(* Logix 5000 project; controller New_CR30 vendor 1 type 14 code 155 rev 21.11; software revision 21.00 *)

TASK MainTask (continuous, watchdog 500 ms) : MainProgram

MODULES
   Local : vendor 1 type 14 code 155 (PointIO 0, rev 21.11)
      CR30 : 440C-CR30-22BBB (Ethernet 192.168.1.30, rev 8.1, Output RPI 60 ms)
      Discrete_IO : Embedded (PointIO 1, rev 21.11, Output RPI 20 ms)
END_MODULES

TYPE STRING_24 :   // string type
STRUCT
   LEN : DINT;
   DATA : SINT[24];
END_STRUCT
END_TYPE

ADD_ON_INSTRUCTION AOI_440C_CR30   (* revision 1.0, vendor Rockwell Automation *)
VAR_INPUT
   Set_FaceplateAnimation : INT;
END_VAR
VAR_OUTPUT
   Sts_Value1 : REAL; {access Read Only}
   Sts_Value2 : REAL; {access Read Only}
   Sts_Value3 : REAL; {access Read Only}
END_VAR
VAR_IN_OUT
   Input_CR30 : AB:440C_CR30:I:0; {required}
   Output_CR30 : AB:440C_CR30:O:0; {required}
END_VAR
VAR_INPUT
   Val_FaultCode : DINT; {visible}
END_VAR
VAR_OUTPUT
   Sts_Value4 : REAL; {access Read Only}
END_VAR
VAR_INPUT
   Val_MinorFaultType : DINT; {required}
   Val_MinorFault : DINT; {required}
   Val_MajorFaultType : DINT; {required}
   Val_MajorFault : DINT; {required}
END_VAR
VAR_OUTPUT
   Sts_ProgramModeEnabled : DINT;
   Sts_CommFault : BOOL; {access Read Only}
   Sts_MinorFault : BOOL; {access Read Only}
   Sts_MajorFault : BOOL; {access Read Only}
   Sts_RunMode : BOOL; {access Read Only}
END_VAR
VAR
   Set_OutputName : STRING_24[25];
   Set_InputName : STRING_24[30] := ([0] := '1');
   Set_DeviceNameOper : STRING := '440C-CR30';
   Val_FaultDescription : STRING_24[30];
   Set_SMFInputName : STRING_24[30];
   Set_SOFInputName : STRING_24[30];
   Val_VerficationID : DINT;
END_VAR

ROUTINE Logic   (* ladder *)
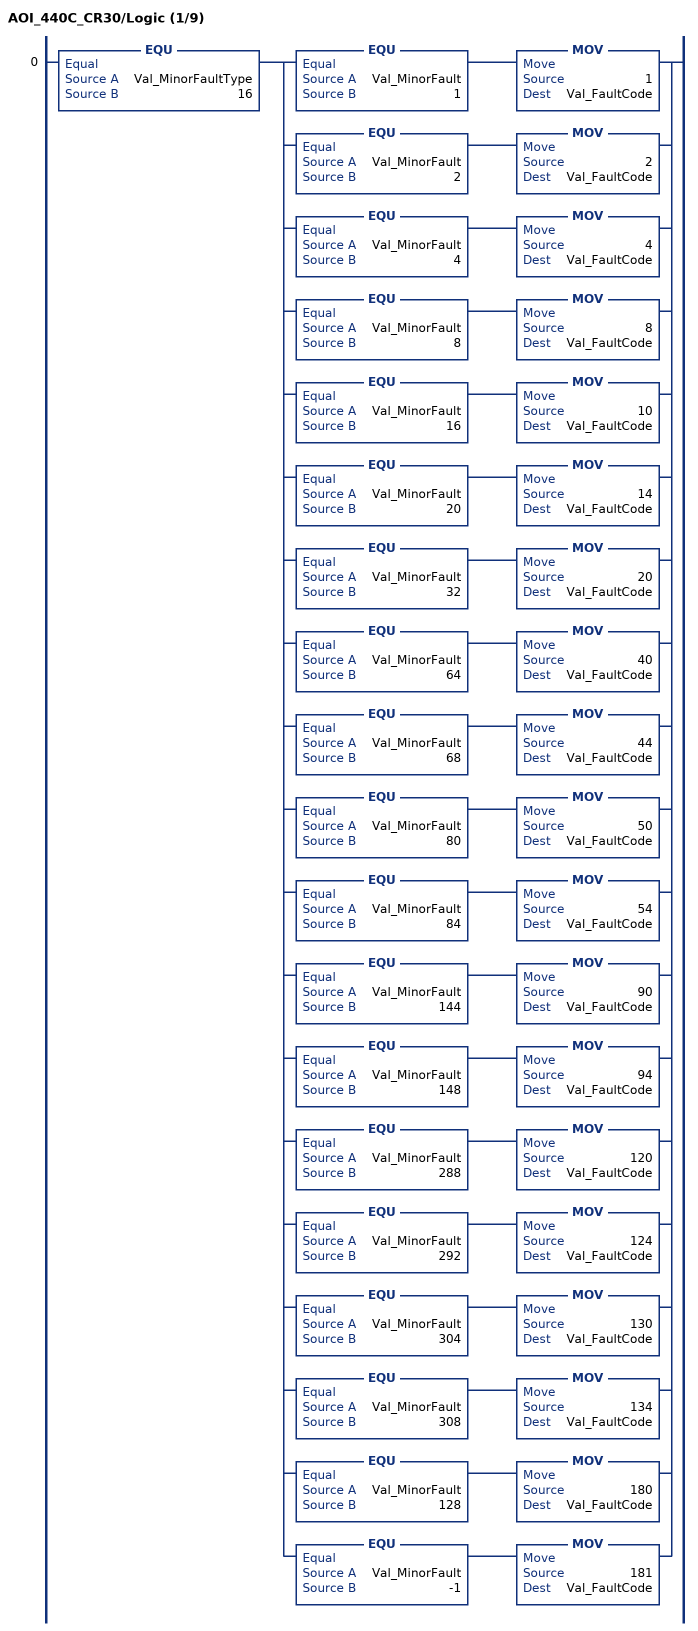
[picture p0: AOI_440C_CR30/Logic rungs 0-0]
   0: EQU(Val_MinorFaultType,16)[EQU(Val_MinorFault,1) MOV(1,Val_FaultCode) ,EQU(Val_MinorFault,2) MOV(2,Val_FaultCode) ,EQU(Val_MinorFault,4) MOV(4,Val_FaultCode) ,EQU(Val_MinorFault,8) MOV(8,Val_FaultCode) ,EQU(Val_MinorFault,16) MOV(10,Val_FaultCode) ,EQU(Val_MinorFault,20) MOV(14,Val_FaultCode) ,EQU(Val_MinorFault,32) MOV(20,Val_FaultCode) ,EQU(Val_MinorFault,64) MOV(40,Val_FaultCode) ,EQU(Val_MinorFault,68) MOV(44,Val_FaultCode) ,EQU(Val_MinorFault,80) MOV(50,Val_FaultCode) ,EQU(Val_MinorFault,84) MOV(54,Val_FaultCode) ,EQU(Val_MinorFault,144) MOV(90,Val_FaultCode) ,EQU(Val_MinorFault,148) MOV(94,Val_FaultCode) ,EQU(Val_MinorFault,288) MOV(120,Val_FaultCode) ,EQU(Val_MinorFault,292) MOV(124,Val_FaultCode) ,EQU(Val_MinorFault,304) MOV(130,Val_FaultCode) ,EQU(Val_MinorFault,308) MOV(134,Val_FaultCode) ,EQU(Val_MinorFault,128) MOV(180,Val_FaultCode) ,EQU(Val_MinorFault,-1) MOV(181,Val_FaultCode) ];
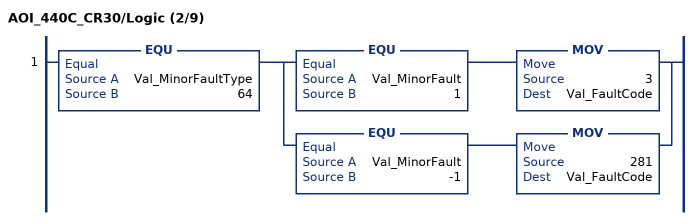
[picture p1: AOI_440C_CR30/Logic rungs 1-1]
   1: EQU(Val_MinorFaultType,64)[EQU(Val_MinorFault,1) MOV(3,Val_FaultCode) ,EQU(Val_MinorFault,-1) MOV(281,Val_FaultCode) ];
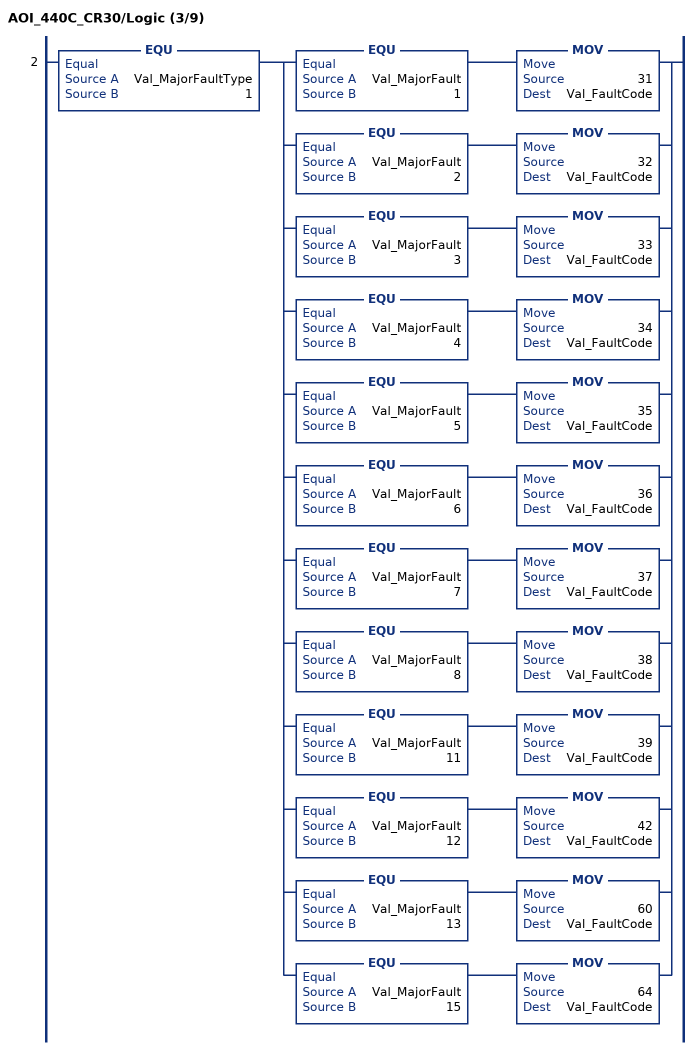
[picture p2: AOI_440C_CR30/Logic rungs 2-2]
   2: EQU(Val_MajorFaultType,1)[EQU(Val_MajorFault,1) MOV(31,Val_FaultCode) ,EQU(Val_MajorFault,2) MOV(32,Val_FaultCode) ,EQU(Val_MajorFault,3) MOV(33,Val_FaultCode) ,EQU(Val_MajorFault,4) MOV(34,Val_FaultCode) ,EQU(Val_MajorFault,5) MOV(35,Val_FaultCode) ,EQU(Val_MajorFault,6) MOV(36,Val_FaultCode) ,EQU(Val_MajorFault,7) MOV(37,Val_FaultCode) ,EQU(Val_MajorFault,8) MOV(38,Val_FaultCode) ,EQU(Val_MajorFault,11) MOV(39,Val_FaultCode) ,EQU(Val_MajorFault,12) MOV(42,Val_FaultCode) ,EQU(Val_MajorFault,13) MOV(60,Val_FaultCode) ,EQU(Val_MajorFault,15) MOV(64,Val_FaultCode) ];
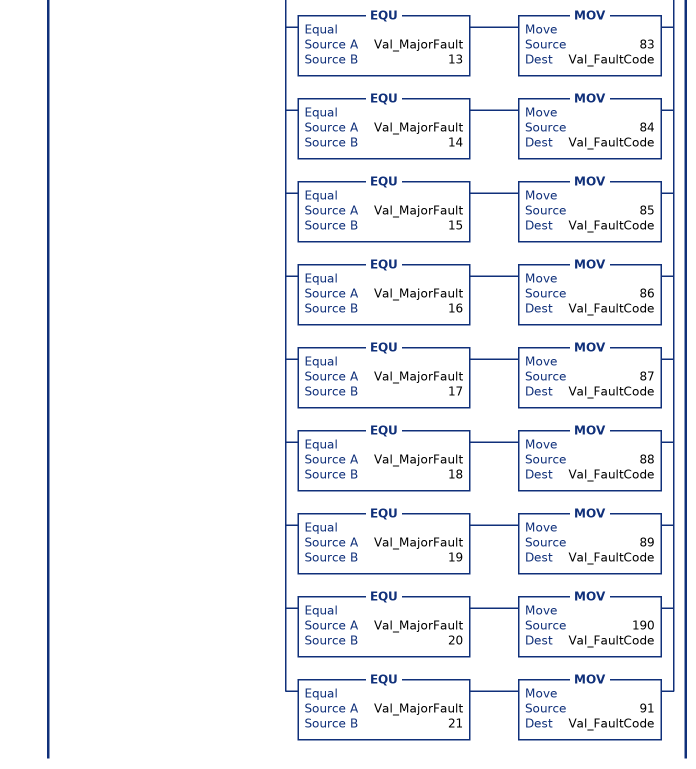
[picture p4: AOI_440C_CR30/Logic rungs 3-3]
   3: EQU(Val_MajorFaultType,2)[EQU(Val_MajorFault,1) MOV(71,Val_FaultCode) ,EQU(Val_MajorFault,2) MOV(72,Val_FaultCode) ,EQU(Val_MajorFault,3) MOV(73,Val_FaultCode) ,EQU(Val_MajorFault,4) MOV(74,Val_FaultCode) ,EQU(Val_MajorFault,5) MOV(75,Val_FaultCode) ,EQU(Val_MajorFault,6) MOV(76,Val_FaultCode) ,EQU(Val_MajorFault,7) MOV(77,Val_FaultCode) ,EQU(Val_MajorFault,8) MOV(78,Val_FaultCode) ,EQU(Val_MajorFault,9) MOV(79,Val_FaultCode) ,EQU(Val_MajorFault,10) MOV(80,Val_FaultCode) ,EQU(Val_MajorFault,11) MOV(81,Val_FaultCode) ,EQU(Val_MajorFault,12) MOV(82,Val_FaultCode) ,EQU(Val_MajorFault,13) MOV(83,Val_FaultCode) ,EQU(Val_MajorFault,14) MOV(84,Val_FaultCode) ,EQU(Val_MajorFault,15) MOV(85,Val_FaultCode) ,EQU(Val_MajorFault,16) MOV(86,Val_FaultCode) ,EQU(Val_MajorFault,17) MOV(87,Val_FaultCode) ,EQU(Val_MajorFault,18) MOV(88,Val_FaultCode) ,EQU(Val_MajorFault,19) MOV(89,Val_FaultCode) ,EQU(Val_MajorFault,20) MOV(190,Val_FaultCode) ,EQU(Val_MajorFault,21) MOV(91,Val_FaultCode) ];
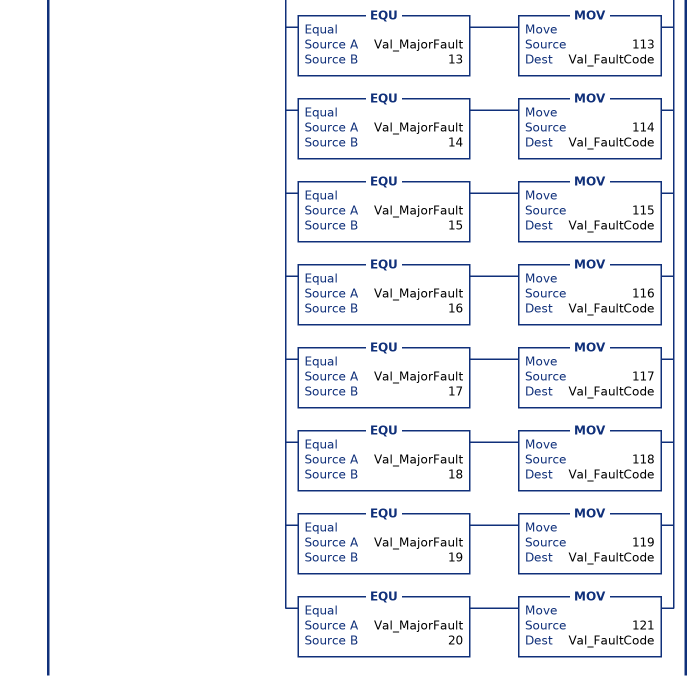
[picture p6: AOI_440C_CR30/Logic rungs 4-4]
   4: EQU(Val_MajorFaultType,4)[EQU(Val_MajorFault,1) MOV(101,Val_FaultCode) ,EQU(Val_MajorFault,2) MOV(102,Val_FaultCode) ,EQU(Val_MajorFault,3) MOV(103,Val_FaultCode) ,EQU(Val_MajorFault,4) MOV(104,Val_FaultCode) ,EQU(Val_MajorFault,5) MOV(105,Val_FaultCode) ,EQU(Val_MajorFault,6) MOV(106,Val_FaultCode) ,EQU(Val_MajorFault,7) MOV(107,Val_FaultCode) ,EQU(Val_MajorFault,8) MOV(108,Val_FaultCode) ,EQU(Val_MajorFault,9) MOV(109,Val_FaultCode) ,EQU(Val_MajorFault,10) MOV(110,Val_FaultCode) ,EQU(Val_MajorFault,11) MOV(111,Val_FaultCode) ,EQU(Val_MajorFault,12) MOV(112,Val_FaultCode) ,EQU(Val_MajorFault,13) MOV(113,Val_FaultCode) ,EQU(Val_MajorFault,14) MOV(114,Val_FaultCode) ,EQU(Val_MajorFault,15) MOV(115,Val_FaultCode) ,EQU(Val_MajorFault,16) MOV(116,Val_FaultCode) ,EQU(Val_MajorFault,17) MOV(117,Val_FaultCode) ,EQU(Val_MajorFault,18) MOV(118,Val_FaultCode) ,EQU(Val_MajorFault,19) MOV(119,Val_FaultCode) ,EQU(Val_MajorFault,20) MOV(121,Val_FaultCode) ];
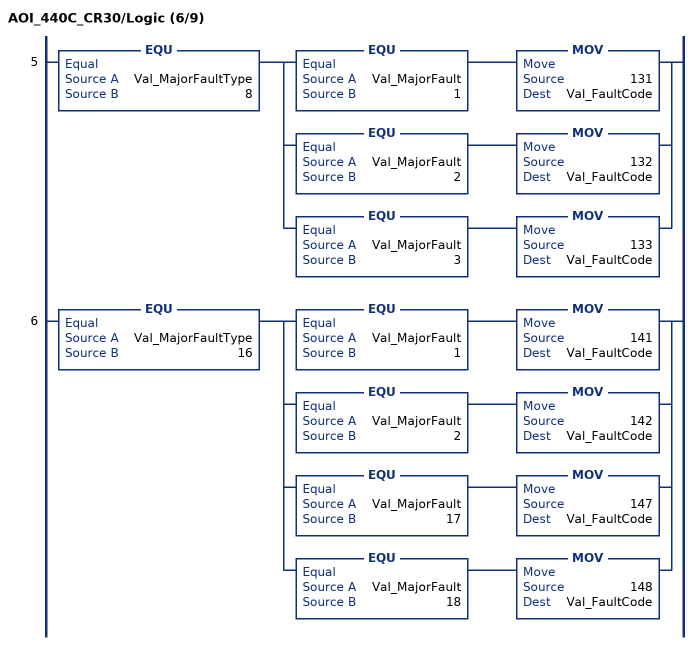
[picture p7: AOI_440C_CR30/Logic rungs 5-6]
   5: EQU(Val_MajorFaultType,8)[EQU(Val_MajorFault,1) MOV(131,Val_FaultCode) ,EQU(Val_MajorFault,2) MOV(132,Val_FaultCode) ,EQU(Val_MajorFault,3) MOV(133,Val_FaultCode) ];
   6: EQU(Val_MajorFaultType,16)[EQU(Val_MajorFault,1) MOV(141,Val_FaultCode) ,EQU(Val_MajorFault,2) MOV(142,Val_FaultCode) ,EQU(Val_MajorFault,17) MOV(147,Val_FaultCode) ,EQU(Val_MajorFault,18) MOV(148,Val_FaultCode) ];
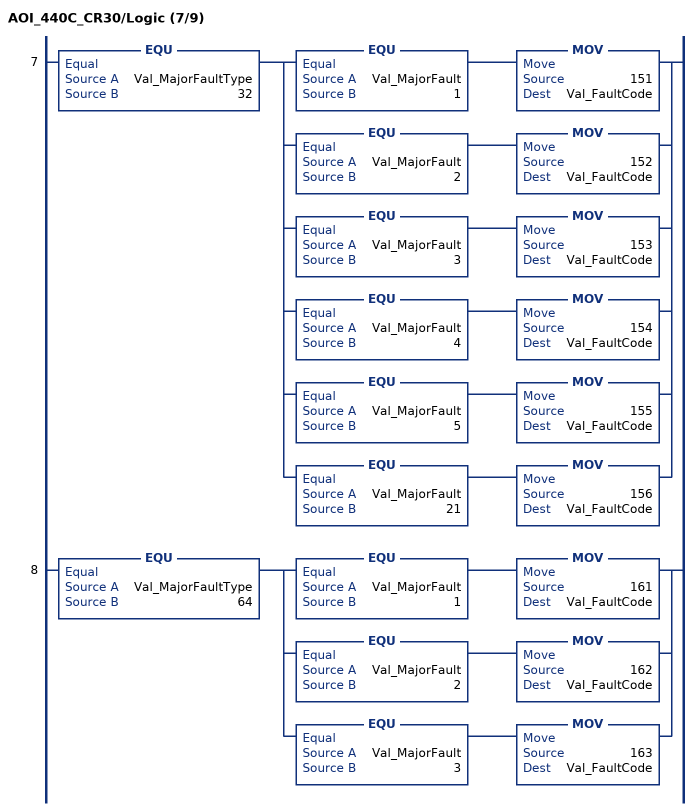
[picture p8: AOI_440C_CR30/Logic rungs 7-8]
   7: EQU(Val_MajorFaultType,32)[EQU(Val_MajorFault,1) MOV(151,Val_FaultCode) ,EQU(Val_MajorFault,2) MOV(152,Val_FaultCode) ,EQU(Val_MajorFault,3) MOV(153,Val_FaultCode) ,EQU(Val_MajorFault,4) MOV(154,Val_FaultCode) ,EQU(Val_MajorFault,5) MOV(155,Val_FaultCode) ,EQU(Val_MajorFault,21) MOV(156,Val_FaultCode) ];
   8: EQU(Val_MajorFaultType,64)[EQU(Val_MajorFault,1) MOV(161,Val_FaultCode) ,EQU(Val_MajorFault,2) MOV(162,Val_FaultCode) ,EQU(Val_MajorFault,3) MOV(163,Val_FaultCode) ];
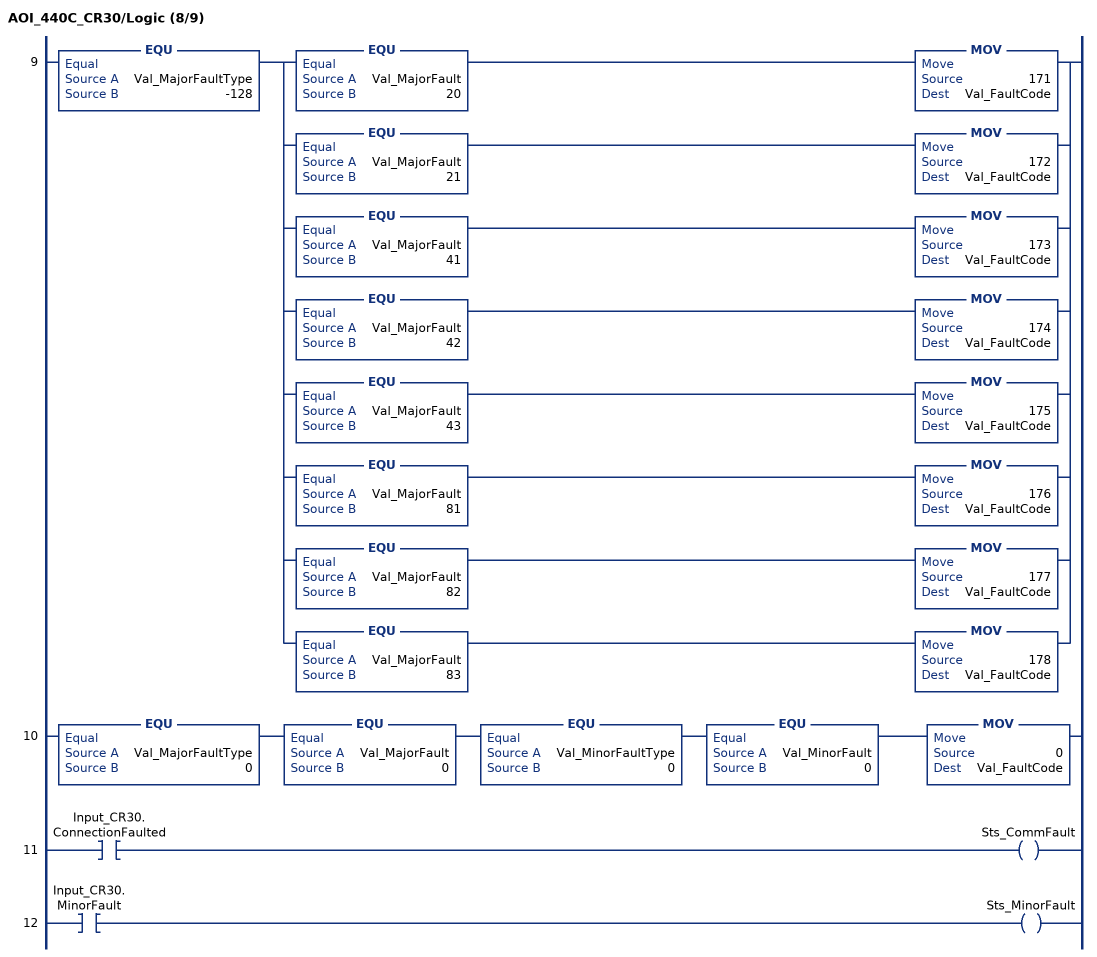
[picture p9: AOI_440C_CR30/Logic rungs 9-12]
   9: EQU(Val_MajorFaultType,-128)[EQU(Val_MajorFault,20) MOV(171,Val_FaultCode) ,EQU(Val_MajorFault,21) MOV(172,Val_FaultCode) ,EQU(Val_MajorFault,41) MOV(173,Val_FaultCode) ,EQU(Val_MajorFault,42) MOV(174,Val_FaultCode) ,EQU(Val_MajorFault,43) MOV(175,Val_FaultCode) ,EQU(Val_MajorFault,81) MOV(176,Val_FaultCode) ,EQU(Val_MajorFault,82) MOV(177,Val_FaultCode) ,EQU(Val_MajorFault,83) MOV(178,Val_FaultCode) ];
   10: EQU(Val_MajorFaultType,0)EQU(Val_MajorFault,0)EQU(Val_MinorFaultType,0)EQU(Val_MinorFault,0)MOV(0,Val_FaultCode);
   11: XIC(Input_CR30.ConnectionFaulted)OTE(Sts_CommFault);
   12: XIC(Input_CR30.MinorFault)OTE(Sts_MinorFault);
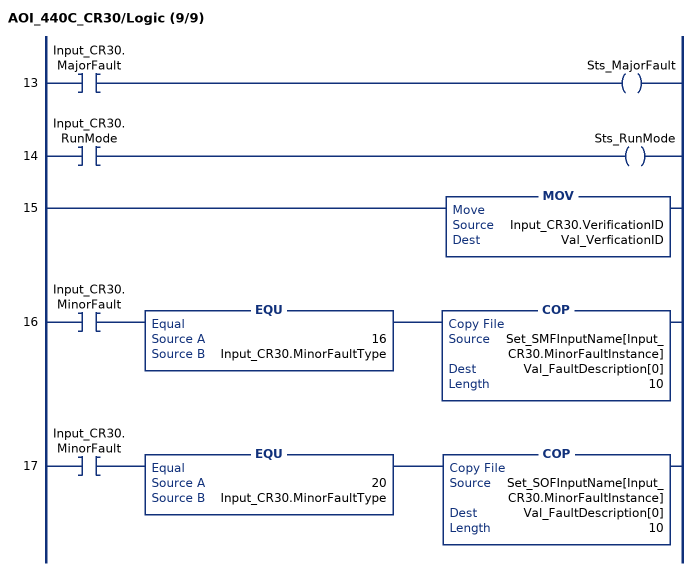
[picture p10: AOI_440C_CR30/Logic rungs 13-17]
   13: XIC(Input_CR30.MajorFault)OTE(Sts_MajorFault);
   14: XIC(Input_CR30.RunMode)OTE(Sts_RunMode);
   15: MOV(Input_CR30.VerificationID,Val_VerficationID);
   16: XIC(Input_CR30.MinorFault)EQU(16,Input_CR30.MinorFaultType)COP(Set_SMFInputName[Input_CR30.MinorFaultInstance],Val_FaultDescription[0],10);
   17: XIC(Input_CR30.MinorFault)EQU(20,Input_CR30.MinorFaultType)COP(Set_SOFInputName[Input_CR30.MinorFaultInstance],Val_FaultDescription[0],10);
END_ROUTINE
END_ADD_ON_INSTRUCTION

VAR_GLOBAL   (* controller tags *)
   CR30 : AOI_440C_CR30;
END_VAR

PROGRAM MainProgram   (* main routine MainRoutine *)

ROUTINE MainRoutine   (* ladder *)
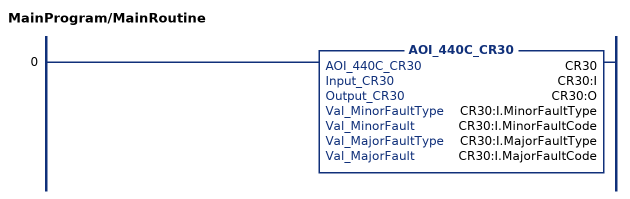
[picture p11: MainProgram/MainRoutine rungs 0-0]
   0: AOI_440C_CR30(CR30,CR30:I,CR30:O,CR30:I.MinorFaultType,CR30:I.MinorFaultCode,CR30:I.MajorFaultType,CR30:I.MajorFaultCode);
END_ROUTINE
END_PROGRAM
